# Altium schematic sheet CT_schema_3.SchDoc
size 293 x 156 mm
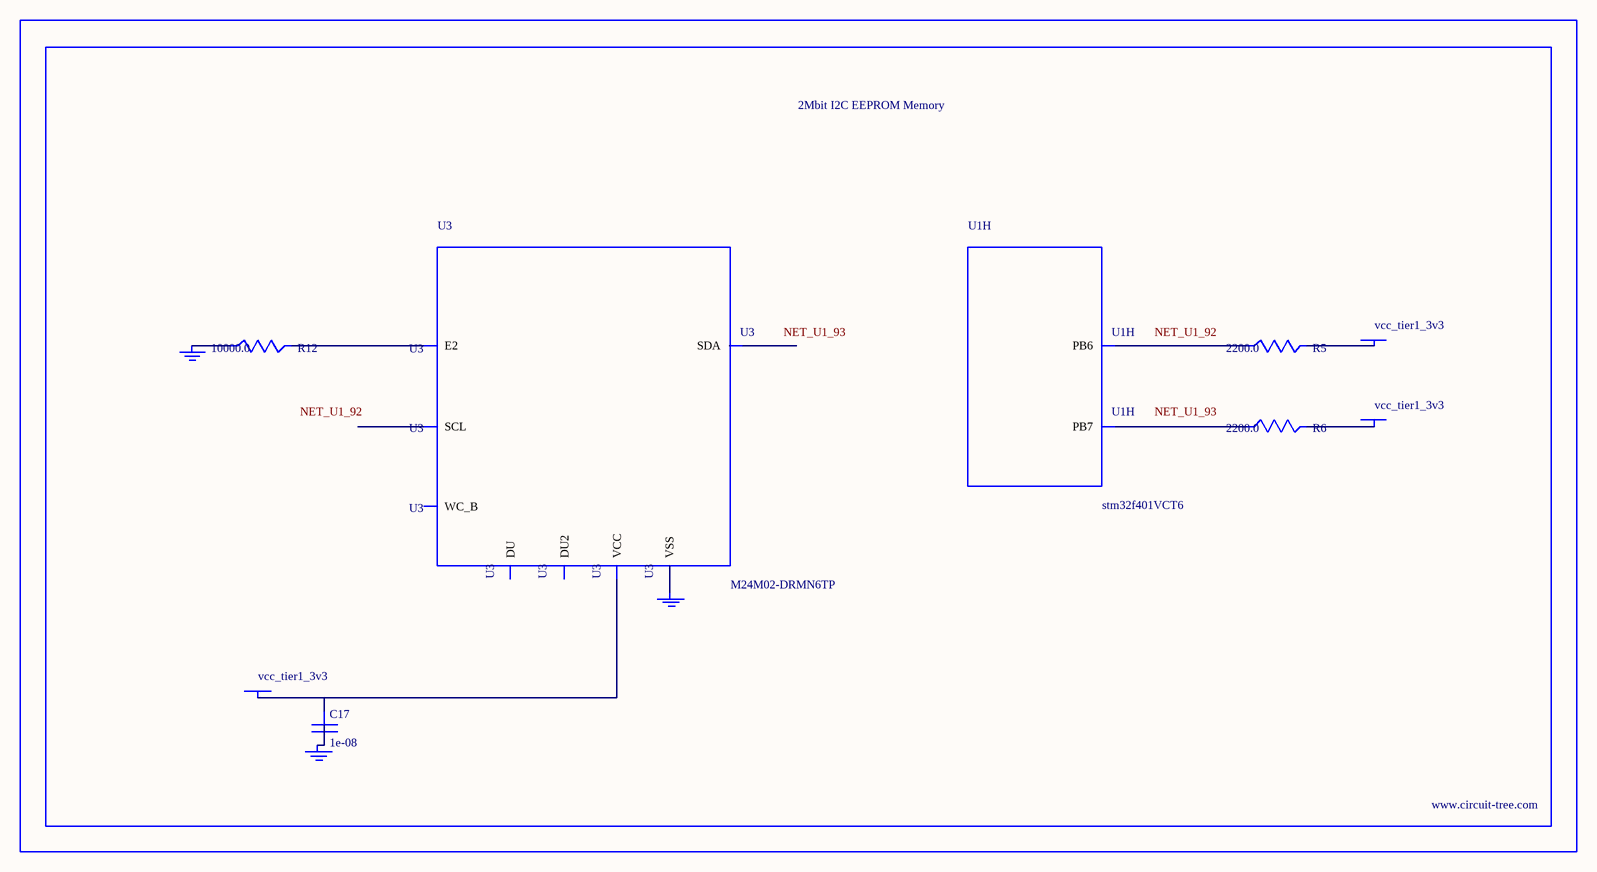
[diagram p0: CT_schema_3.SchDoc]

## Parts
BORDER2  (no value)
C17  1e-08  [C0402]
GND_INSTANCE_2_0  (no value)
GND_INSTANCE_2_1  (no value)
GND_INSTANCE_2_2  (no value)
POWER_INSTANCE_2_0  vcc_tier1_3v3
POWER_INSTANCE_2_1  vcc_tier1_3v3
POWER_INSTANCE_2_2  vcc_tier1_3v3
R5  2200.0  [R0603]
R6  2200.0  [R0603]
R12  10000.0  [R0603]
U1  stm32f401VCT6  [LQFP100]  (part H of 11)
U3  M24M02-DRMN6TP  [SOIC-8]

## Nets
NetC17_1: C17.1 POWER_INSTANCE_2_0.0(PWR) U3.8(VCC)
NetC17_2: C17.2 GND_INSTANCE_2_1.0(GND)
NetGND_INSTANCE_2_0_0: GND_INSTANCE_2_0.0(GND) R12.1
NetGND_INSTANCE_2_2_0: GND_INSTANCE_2_2.0(GND) U3.4(VSS)
NetPOWER_INSTANCE_2_1_0: POWER_INSTANCE_2_1.0(PWR) R5.2
NetPOWER_INSTANCE_2_2_0: POWER_INSTANCE_2_2.0(PWR) R6.2
NetR5_1: R5.1 U1.92(PB6)
NetR6_1: R6.1 U1.93(PB7)
NetR12_2: R12.2 U3.3(E2)

Not connected (* = marked no-connect by the designer): U3 1(DU) 2(DU2) 5(SDA) 6(SCL) 7(WC_B)

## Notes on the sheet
- Labels drawn without touching a wire or pin: NET_U1_92, NET_U1_93

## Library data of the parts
BORDER2 = BORDER_PAGE2
C17 = C0402C103K3RAC
GND_INSTANCE_2_0-GND_INSTANCE_2_2 = GND
POWER_INSTANCE_2_0-POWER_INSTANCE_2_2 = PWR
R5 R6 = RC0603JR-072K2L
R12 = RC0603JR-0710KL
